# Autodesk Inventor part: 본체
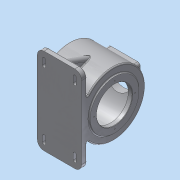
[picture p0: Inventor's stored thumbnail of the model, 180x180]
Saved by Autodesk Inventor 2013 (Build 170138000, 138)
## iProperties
Created: 2015-06
Part Number: 본체
Material: 알루미늄 6061
Document SubType Name: Modeling
Designer: dgall
Density: 2.71 g/cm^3
Mass: 3276.59 g
Surface Area: 2301.97 cm^2
Volume: 1209.07 cm^3
Author: dgall
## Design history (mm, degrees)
sketch "스케치1"
  geometry: L1 (0, 0)-(134, 0); L2 (134, 47.5)-(134, 65); L3 (134, 65)-(131, 65); L4 (131, 65)-(131, 85); L5 (131, 85)-(13, 85); L6 (13, 85)-(13, 65); L7 (13, 65)-(0, 65); L8 (0, 65)-(0, 0); L9 (134, 47.5)-(123, 47.5); L10 (123, 47.5)-(123, 77); L11 (123, 77)-(21, 77); L12 (21, 77)-(21, 31); L13 (21, 31)-(24.5, 29.368); L14 (24.5, 29.368)-(24.5, 23.5); L15 (24.5, 23.5)-(10.5, 23.5); L16 (10.5, 23.5)-(10.5, 15); L17 (10.5, 15)-(7.5, 15); L18 (7.5, 15)-(7.5, 0)
  constraints: 36 end point, 7 parallel, 7 perpendicular, 1 collinear, 1 horizontal, 1 point on line, 1 vertical, 1 vertical alignment
  dimensions: "d0" = 170 diameter of L5 L1; "d2" = 130 diameter of L7 L1; "d3" = 130 diameter of L3 L1; "d4" = 134 distance of L1.start L1.end; "d5" = 13 distance of L6.end L7.end; "d6" = 3 distance of L2.end L3.end; "d7" = 11 distance of L2.start L9.end; "d8" = 95 diameter of L9 L1; "d9" = 154 diameter of L11 L1; "d10" = 8 distance between parallel lines of L12 L6; "d11" = 115 deg angle of L12 L13; "d12" = 62 diameter of L12.end L1; "d13" = 3.5 distance between parallel lines of L12 L14; "d14" = 14 distance of L14.end L15.end; "d15" = 30 diameter of L17 L1; "d16" = 47 diameter of L15 L1; "d17" = 3 distance of L16.end L17.end
revolve "회전1" sketch "스케치1" stored, may be unused: angle "d18" = 90 deg
fillet "모깎기1" dims "d19" = 3
fillet "모깎기2" dims "d20" = 0.3
fillet "모깎기3" dims "d21" = 3
fillet "모깎기4" dims "d22" = 3
node "작업 평면1"
sketch "스케치2"
  geometry: L1 (-114.5, 42.5)-(-29.5, 42.5); L2 (-29.5, 42.5)-(-29.5, -42.5); L3 (-29.5, -42.5)-(-114.5, -42.5); L4 (-114.5, -42.5)-(-114.5, 42.5); L5 (-13, 85)-(-13, -85) reference; C1 r 35 at (-72, 0); 3 further points
  constraints: 8 end point, 2 horizontal alignment, 2 midpoint, 2 parallel, 2 perpendicular, 1 centre point, 1 horizontal, 1 vertical alignment
  dimensions: "d24" = 59 distance from line of L5 C1.centre; "d25" = 85 distance of L1.start L1.end; "d26" = 70 diameter of C1
extrude "돌출1" join sketch "스케치2" stored distance "d27" = 10; taper "d28" = 0 deg
extrude "돌출2" cut sketch "스케치2" stored distance "d29" = 10; taper "d30" = 0 deg
fillet "모깎기5" dims "d31" = 7
chamfer "모따기1" distance "d32" = 1; stored, may be unused: second distance "d33" = 2, angle "d34" = 45 deg
sketch "스케치3"
  geometry: C1 r 36 at (72, 0) reference; 5 further points
  constraints: 2 horizontal alignment, 2 vertical alignment
  dimensions: "d35" = 71 distance of point (107.5, -35.5) point (107.5, 35.5); "d37" = 71 distance of point (36.5, 35.5) point (107.5, 35.5); "d38" = 35.5 horizontal distance of C1.centre point (107.5, -35.5); "d39" = 35.5 horizontal distance of C1.centre point (107.5, -35.5)
hole "구멍1" sketch "스케치3" at (36.5, 35.5), (107.5, 35.5), (107.5, -35.5), (36.5, -35.5) diameter "d40" = 3.242; stored, may be unused: countersink angle "d44" = 90 deg, drill point angle "d46" = 118 deg; dims "d41" = 10, "d42" = 4, "d43" = 2, "d45" = 13
sketch "스케치4"
  geometry: C1 r 47.5 at (0, 0) reference; 1 further point
  constraints: 1 vertical alignment
  dimensions: "d47" = 55 distance of C1.centre point (0, 55)
hole "구멍2" sketch "스케치4" at (0, 55) diameter "d48" = 3.242; stored, may be unused: countersink angle "d52" = 90 deg, drill point angle "d54" = 118 deg; dims "d49" = 10, "d50" = 4, "d51" = 2, "d53" = 13
fillet "모깎기6" dims "d58" = 3
chamfer "모따기2" distance "d60" = 1; stored, may be unused: second distance "d61" = 2, angle "d62" = 45 deg
node "작업 평면2"
sketch "스케치7"
  geometry: 1 further point
node "작업 평면7"
sketch "스케치13"
  geometry: L1 (115, -71)-(-115, -71); L2 (-115, -71)-(-115, -85); L3 (-115, -85)-(115, -85); L4 (115, -85)-(115, -71); L5 (109, -71)-(84.87, -4.703); L6 (-109, -71)-(-84.87, -4.703); A1 r 85 centre (0, 0) between (84.87, -4.703) and (-84.87, -4.703) reference; 2 further points
  constraints: 12 end point, 2 parallel, 2 point on circle, 2 point on line, 1 horizontal, 1 midpoint, 1 perpendicular, 1 vertical alignment
  dimensions: "d104" = 14 distance of L1.end L2.end; "d106" = 85 distance from line of L3 point (0, 0); "d107" = 230 distance of L2.end L3.end; "d108" = 6 distance from line of L5.start L4; "d109" = 110 deg angle of L1 L5; "d110" = 6 distance from line of L2 L6.start; "d111" = 110 deg angle of L1 L6
extrude "돌출8" join sketch "스케치13" stored distance "d112" = 118; taper "d113" = 0 deg
feature "리브3" dims "d114" = 1, "d115" = 15, "d116" = 0, "d117" = 0, "d118" = 1, "d119" = 1
feature "리브4" dims "d120" = 1, "d121" = 15, "d122" = 0, "d123" = 0, "d124" = 1, "d125" = 1
fillet "모깎기12" dims "d126" = 18
fillet "모깎기13" dims "d127" = 7.5
sketch "스케치14"
  geometry: L1 (91, 212)-(91, 196); L2 (73, 212)-(73, 196); L3 (86, 212)-(86, 196); L4 (78, 212)-(78, 196); A1 r 18 centre (82, 212) between (100, 212) and (82, 230) reference; A2 r 9 centre (82, 212) between (91, 212) and (73, 212); A3 r 9 centre (82, 196) between (73, 196) and (91, 196); A4 r 4 centre (82, 212) between (86, 212) and (78, 212); A5 r 4 centre (82, 196) between (78, 196) and (86, 196); 1 further point
  constraints: 8 end point, 8 point on circle, 8 tangent, 4 centre point, 3 coincident, 2 equal radius, 1 vertical alignment
  dimensions: "d128" = 18 diameter of A2; "d130" = 16 distance of A3.centre A2.centre; "d131" = 8 diameter of A4
extrude "돌출9" join sketch "스케치14" distance "d132" = 17; taper "d133" = 0 deg
extrude "돌출10" cut sketch "스케치14" distance "d134" = 17; taper "d135" = 0 deg
node "작업 평면8"
node "작업 평면9"
fillet "모깎기14" dims "d136" = 3
fillet "모깎기15" dims "d137" = 3
fillet "모깎기16" dims "d138" = 3
fillet "모깎기17" dims "d139" = 3
fillet "모깎기18" dims "d140" = 3
fillet "모깎기19" dims "d141" = 3
fillet "모깎기20" dims "d142" = 3
node "작업 평면10"
sketch "스케치15"
  geometry: L1 (76.143, 14)-(117.857, 14) reference; L2 (126.799, 14)-(67.201, 14); A1 r 77 centre (97, 85) between (126.799, 14) and (67.201, 14) reference; A2 r 77 centre (97, 85) between (67.201, 14) and (126.799, 14); 1 further point
  constraints: 2 end point, 2 point on circle, 1 centre point, 1 coincident, 1 collinear, 1 point on line
extrude "돌출11" cut sketch "스케치15" stored distance "d143" = 102; taper "d144" = 0 deg
fillet "모깎기21" dims "d145" = 3
node "작업 평면11"
sketch "스케치16"
  geometry: L1 (97, 85)-(201.164, 85); L2 (97, 85)-(205.502, 135.595)
  constraints: 4 end point, 1 horizontal
  dimensions: "d146" = 25 deg angle of L1 L2
node "작업 평면12"
node "작업 평면13"
sketch "스케치17"
  geometry: 3 further points
  constraints: 2 coincident, 1 other
feature "엠보싱2" sketch "스케치17" dims "d16" = 47, "d147" = 0.5, "d148" = 0
node "솔리드1"
pattern_circular "원형 패턴1" dims angle "d56" = 360 deg
mirror "대칭3"
mirror "대칭4"
other parameters: "d23" = 88
